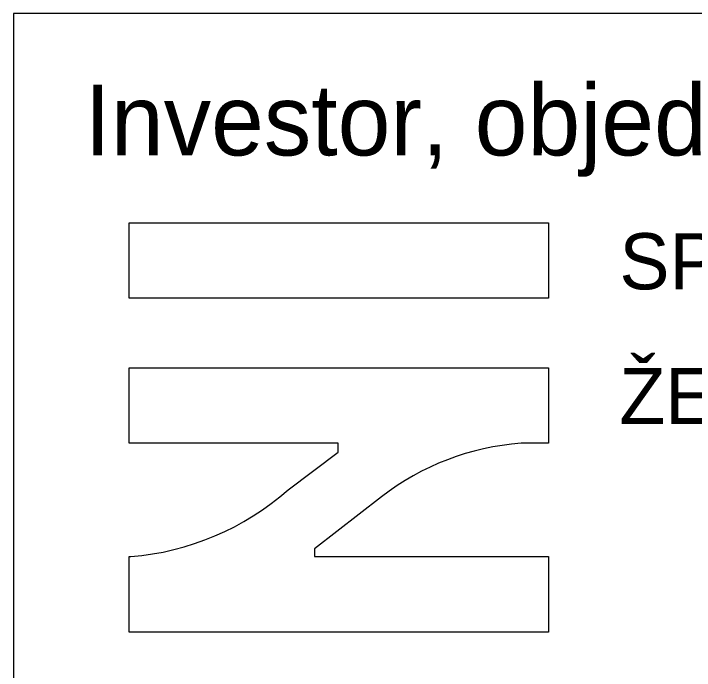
# Model space of a CAD drawing. Extents: x 563 to 1437, y -18 to 279.
# Drawn here: x 1068.34 to 1087.53, y 72.88 to 91.4 of the extents above; entities that cross this region are included whole.
import ezdxf

# ---------------------------------------------------------------- set-up
doc = ezdxf.new("R2010")
doc.units = 0
for name, color, linetype in [('ROZPISKA', 7, 'Continuous'), ('Rozpiska_Logo', 7, 'Continuous'), ('Rozpiska_pole_6', 7, 'Continuous')]:
    doc.layers.add(name, color=color, linetype=linetype)

# ---------------------------------------------------------------- blocks, each defined once
blk = doc.blocks.new('_U1')
at = {"layer": 'Rozpiska_Logo'}
blk.add_lwpolyline([(-0.008400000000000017, 0.008199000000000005), (0.008399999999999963, 0.008199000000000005), (0.008399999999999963, 0.005175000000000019), (-0.008400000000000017, 0.005175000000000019)], close=True, dxfattribs=at)
for points in [[(-2.9958344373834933e-05, -0.0006329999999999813), (-0.008400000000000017, -0.0006329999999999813), (-0.008400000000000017, 0.00239099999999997), (0.008399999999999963, 0.00239099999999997), (0.008399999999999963, -0.0006329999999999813), (0.007294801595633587, -0.0006329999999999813)], [(-0.0020291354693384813, -0.0024975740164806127), (-2.9958344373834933e-05, -0.0009900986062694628), (-2.9958344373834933e-05, -0.0006329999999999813)], [(0.001714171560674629, -0.0027749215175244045), (-0.0009743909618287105, -0.004858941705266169), (-0.0009743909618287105, -0.005174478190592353), (0.008399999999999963, -0.005174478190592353), (0.008399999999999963, -0.008198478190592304), (-0.008400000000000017, -0.008198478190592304), (-0.008400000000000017, -0.005174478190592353), (-0.00833142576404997, -0.005174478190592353)]]:
    blk.add_lwpolyline(points, dxfattribs=at)
for centre, radius, start, end in [((0.008055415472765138, -0.010955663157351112), 0.010350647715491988, 94.21415970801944, 127.78079967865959), ((-0.009201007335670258, 0.0056300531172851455), 0.010839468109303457, 274.6014205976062, 311.4253943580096)]:
    blk.add_arc(centre, radius, start, end, dxfattribs=at)
blk = doc.blocks.new('_U0')
at = {"layer": 'Rozpiska_Logo'}
blk.add_blockref('_U1', (-0.011064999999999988, -0.00035550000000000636), dxfattribs=at)
at = {"layer": 'Rozpiska_pole_6'}
for s, p in [('SPRÁVA', (0.00016969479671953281, 0.005179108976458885)), ('ŽELEZNIC', (0.00016969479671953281, -0.00022089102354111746))]:
    blk.add_text(s, height=0.0022500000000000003, dxfattribs=at).set_placement(p)

msp = doc.modelspace()

# ---------------------------------------------------------------- linework, layer by layer
at = {"layer": 'ROZPISKA'}
msp.add_lwpolyline([(1238.341445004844, -5.598027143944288), (1238.341445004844, 91.40197285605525), (1068.341445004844, 91.40197285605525), (1068.341445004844, -5.598027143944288)], close=True, dxfattribs=at)

# ---------------------------------------------------------------- block references
at = {"layer": 'Rozpiska_Logo', "xscale": 704.0000000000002, "yscale": 704.0000000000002}
msp.add_blockref('_U0', (1085.3004726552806, 79.97760014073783), dxfattribs=at)
msp.add_blockref('_U0', (1085.3004726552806, 79.97760014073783), dxfattribs=at)

# ---------------------------------------------------------------- texts
at = {"layer": 'ROZPISKA'}
msp.add_text('Investor, objednatel :', height=2, dxfattribs=at).set_placement((1070.341445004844, 87.40197285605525))
msp.add_text('Investor, objednatel :', height=2, dxfattribs=at).set_placement((1070.341445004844, 87.40197285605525))
msp.add_text('Investor, objednatel :', height=2, dxfattribs=at).set_placement((1070.341445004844, 87.40197285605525))
msp.add_text('Investor, objednatel :', height=2, dxfattribs=at).set_placement((1070.341445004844, 87.40197285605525))
msp.add_text('Investor, objednatel :', height=2, dxfattribs=at).set_placement((1070.341445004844, 87.40197285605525))

doc.saveas('drawing.dxf')
